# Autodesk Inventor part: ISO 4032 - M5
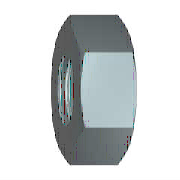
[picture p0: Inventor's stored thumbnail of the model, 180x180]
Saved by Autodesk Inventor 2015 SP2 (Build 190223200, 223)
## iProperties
IsCustomPart: 0
Created: 2012-02
Part Number: ISO 4032 - M5
Material: Edelstahl, 440C
Description: Sechskantmuttern, Typ 1 - Produktklasse A und B
Document SubType Name: Modeling
Standard: ISO 4032
Designer: Dan
Standard Revision: Third edition 1999-08-15
Standards Organization: ISO
Language: de-DE
Size Designation: M5
Categories: <MemberInstance><Categories><Category DisplayName="Verbindungselemente" InternalName="e4da775c-781d-43d5-af7c-5136215cf5a6" Mnemonic="FSTN"><Category DisplayNam
Density: 7.75 g/cm^3
Appearance: Halbpoliert
Author: Dan
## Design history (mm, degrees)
sketch "Skizze1"
  geometry: L1 (-4.619, 0)-(-2.309, 4); L2 (-2.309, 4)-(2.309, 4); L3 (2.309, 4)-(4.619, 0); L4 (4.619, 0)-(2.309, -4); L5 (2.309, -4)-(-2.309, -4); L6 (-2.309, -4)-(-4.619, 0); 2 further points
  constraints: 12 end point, 1 coincident, 1 horizontal, 11 other
  dimensions: "d0" = 9.2376 distance of L3.end L1.start (= 1.1547 x SW)
extrude "Körper" new body sketch "Skizze1" distance "d1" = 4.7 (= KOH); taper "d2" = 0 deg
sketch "Skizze2"
  geometry: L1 (0, 2.309)-(0, 4.619) reference; L2 (0, 4.619)-(4.7, 4.619) reference; L3 (4.7, 2.309)-(4.7, 4.619) reference; L4 (-0.94, 0)-(5.64, 0) reference; L5 (0.675, 4.619)-(0, 3.45); L6 (4.025, 4.619)-(4.7, 3.45)
  constraints: 4 end point, 4 point on line
  dimensions: "d3" = 30 deg angle of L1 L5 (= ANG1); "d4" = 30 deg angle of L3 L6 (= ANG2); "d5" = 6.9 diameter of L5.end L4 (= SW0); "d6" = 6.9 diameter of L6.end L4 (= SW01)
revolve "Fase1" sketch "Skizze2" stored, may be unused: angle "d7" = 90 deg
sketch "Skizze3"
  geometry: 4 further points
  constraints: 1 coincident, 1 other
hole "Gewinde" sketch "Skizze3" at (0, 0) diameter "d25" = 4.134; stored, may be unused: countersink angle "d29" = 82 deg, drill point angle "d31" = 118 deg; dims "d26" = 6, "d27" = 4, "d28" = 2, "d30" = 8
workaxis "Work Axis1"
workplane "Work Plane1"
body "Solid1"
chamfer "Fase2" distance "d8" = 0.43301 (= -0.5 x GD1 + 0.5 x NND); stored, may be unused: angle "d9" = 30 deg, second distance "d40" = 0.43301 (= -0.5 x GD1 + 0.5 x NND)
chamfer "Fase3" distance "d10" = 0.43301 (= -0.5 x GD1 + 0.5 x NND); stored, may be unused: angle "d11" = 30 deg, second distance "d41" = 0.43301 (= -0.5 x GD1 + 0.5 x NND)
other parameters: "ANG1" = 30 deg [user parameter; used in 1 equation term], "ANG2" = 30 deg [user parameter; used in 1 equation term], "NND" = 5 [user parameter; used in 4 equation terms], "KOH" = 4.7 [user parameter; used in 1 equation term], "SW" = 8 [user parameter; used in 2 equation terms], "SW0" = 6.9 [user parameter; used in 2 equation terms], "SW01" = 6.9 (= SW0) [user parameter; used in 1 equation term], "GD1" = 4.13397 (computed from THREADDIA, PTC, TOA) [user parameter; used in 4 equation terms], "d13" = 0, "d14" = 0, "d39" = 0, "d42" = 0, "GUL" = 0.43301 (= 0.541266 x PTC) [user parameter], "TPU" = 12.5 (computed from PTC) [user parameter], "THREADDIA" = 5 [user parameter; used in 1 equation term], "TOA" = 30 deg [user parameter; used in 1 equation term], "PTC" = 0.8 [user parameter; used in 4 equation terms], "E0" = 9.24 (= 1.155 x SW) [user parameter], "GAL" = 0.43301 (= 0.541266 x PTC) [user parameter]
